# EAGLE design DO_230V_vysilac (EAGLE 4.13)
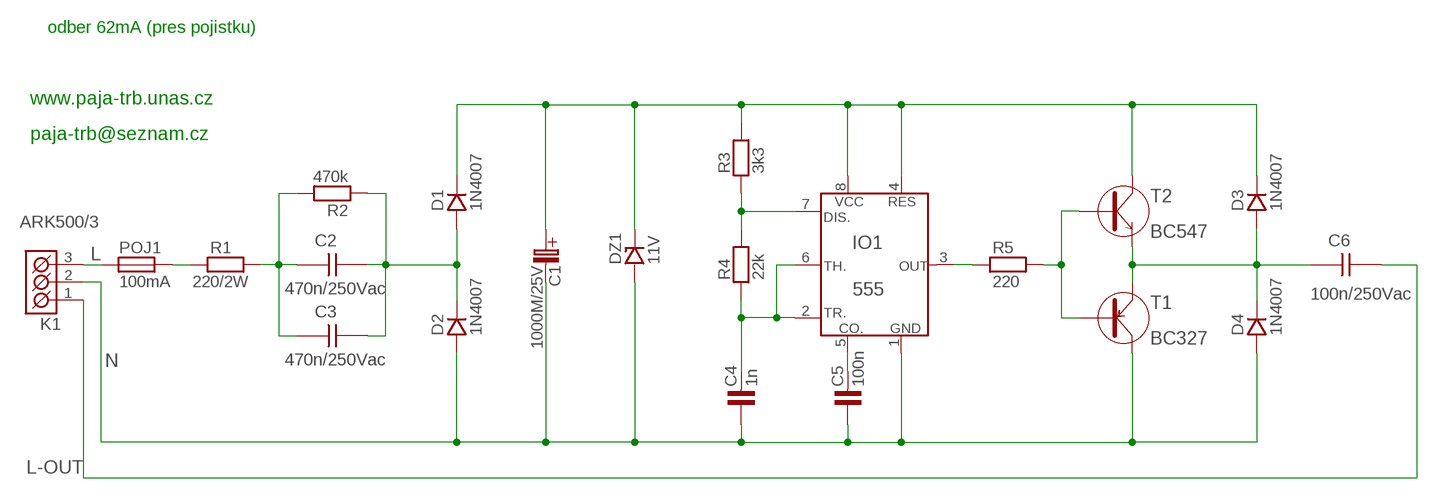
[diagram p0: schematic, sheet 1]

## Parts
C1  1000M/25V  [C_EL_5+]
C2  470n/250Vac  CFAC-15,0  [CFAC-15]
C3  470n/250Vac  CFAC-15,0  [CFAC-15]
C4  1n  C-KERAMIK_5  [C-5]
C5  100n  C-KERAMIK_5  [C-5]
C6  100n/250Vac  CFAC-15,0  [CFAC-15]
D1  1N4007  1N4007_10  [D-10]
D2  1N4007  1N4007_10  [D-10]
D3  1N4007  1N4007_10  [D-10]
D4  1N4007  1N4007_10  [D-10]
DZ1  11V  D-ZENEROVA_1,3W_BZX85V  [D-7,5]
IO1  555  [DIL8]
K1  ARK500/3  [ARK500/3]
POJ1  100mA  PO_SHH  [POJ_SHH]
R1  220/2W  R__2W  [R-_2W]
R2  470k  R_7,5  [R-7,5]
R3  3k3  R_7,5  [R-7,5]
R4  22k  R_7,5  [R-7,5]
R5  220  R_7,5  [R-7,5]
T1  BC327  [TO-92]
T2  BC547  BC546  [TO-92]

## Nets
A: C2.1 C3.1 R1.2 R2.2
L: K1.3(K3) POJ1.L1
L-IN: POJ1.P1 R1.1
L-OUT: C6.2 K1.1(K1)
N: C1.C-(C_EL-) C4.1 C5.1 D2.A D4.A DZ1.A IO1.1(GND) K1.2(K2) T1.1(C)
N$1: C4.2 IO1.2(TR.) IO1.6(TH.) R4.1
N$2: IO1.7(DIS.) R3.1 R4.2
N$4: IO1.3(OUT) R5.1
N$6: R5.2 T1.2(B) T2.2(B)
N$8: C6.1 D3.A D4.K T1.3(E) T2.3(E)
N$10: C5.2 IO1.5(CO.)
N$13: C1.C+(C_EL+) D1.K D3.K DZ1.K IO1.4(RES) IO1.8(VCC) R3.2 T2.1(C)
N$14: C2.2 C3.2 D1.A D2.K R2.1

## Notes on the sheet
- odber 62mA (pres pojistku)
- www.paja-trb.unas.cz
- paja-trb@seznam.cz

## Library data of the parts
C1 = #PaJa_C-el:1000M/25V
C2 C3 C6 = #_GM99:CFAC-15,0
C4 C5 = #PaJa_20:C-KERAMIK: Kondenzator - keramicky
D1-D4 = #PaJa_20:1N4007: Usmernovaci dioda - 1A, 1000V
DZ1 = #PaJa_20:D-ZENEROVA: Zenerova dioda
IO1 = #PaJa_20:555: IO - Casovac 555
K1 = #PaJa_20:ARK500/3: Svorkovnice - roztec 5mm - trojita
POJ1 = #PaJa_20:PO_SHH: Pojistkove pouzdro
R1-R5 = #PaJa_20:R: Rezistor
T1 = #PaJa_20:BC327: Tranzistor PNP - Univerzalni NF - Ic=0,5A
T2 = #PaJa_20:BC546: Tranzistor NPN - Univerzalni NF - Ic=0,1A

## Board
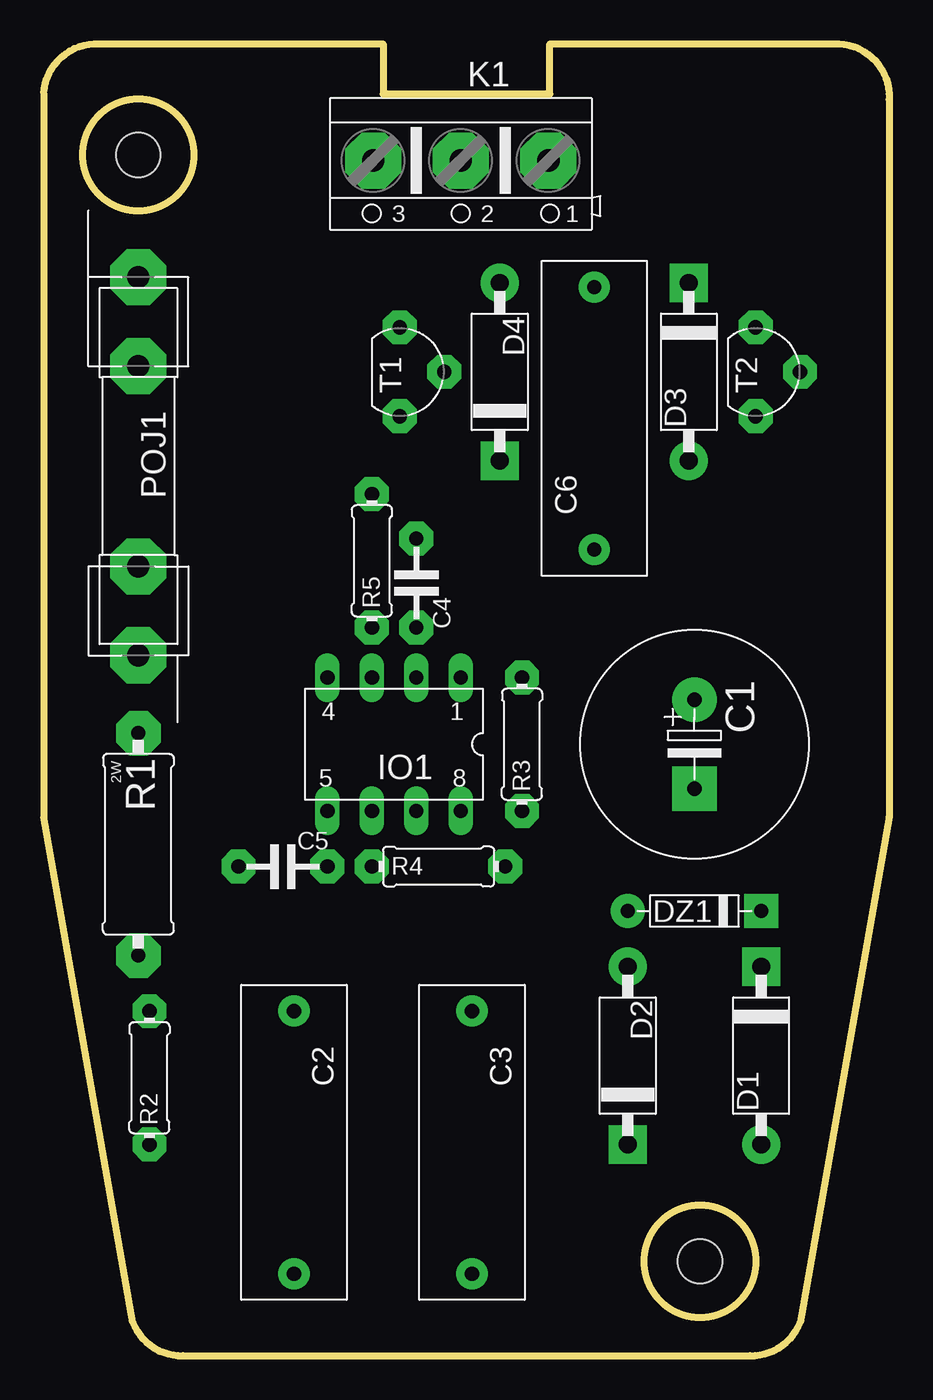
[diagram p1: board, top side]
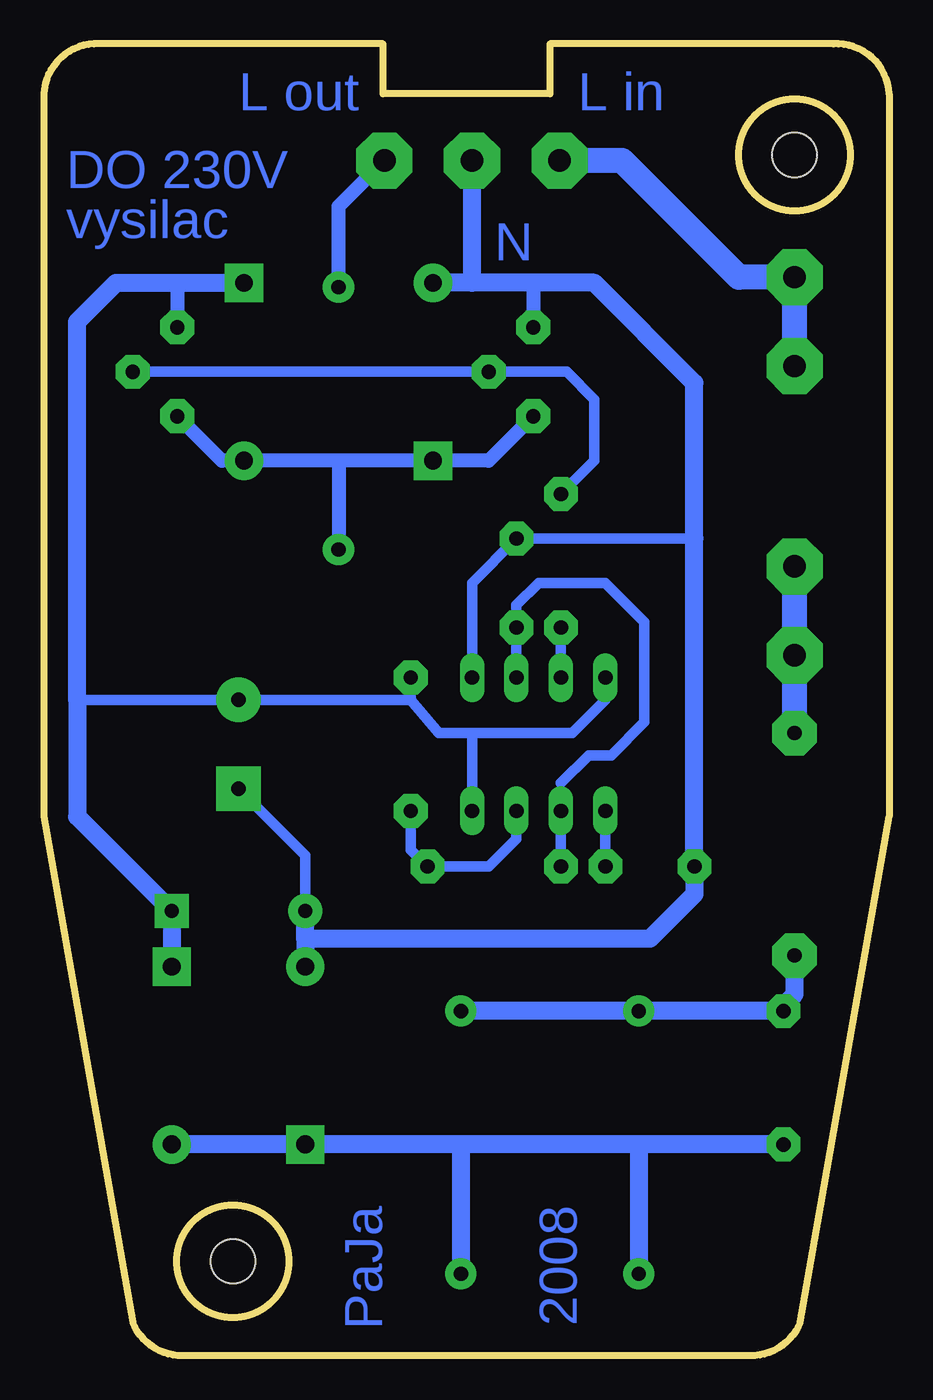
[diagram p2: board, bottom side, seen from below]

Size 48.26 x 74.93 mm. Coordinates in mm from the lower left corner, seen from the top.
Copper layers (1*16): Top 0.035mm / dielectric 1.5mm / Bottom 0.035mm
Design rules "default": minimum track width 10mil, minimum drill 24mil, track to track 8mil, track to pad 8mil, pad to pad 8mil, via to via 8mil, smd to smd 8mil, copper to edge 40mil, drill to drill 8mil, minimum pad ring 10mil, minimum via ring 8mil, stop-mask expansion 4mil, vias tented up to drill 0mil, thermal gap 10mil

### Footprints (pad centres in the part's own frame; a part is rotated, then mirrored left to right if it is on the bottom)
C_EL_5+ = drill 0.813 pad 2.54 round: C+ -2.54,0 | drill 0.813 pad 2.54 square: C- 2.54,0
CFAC-15 = drill 0.813 pad 1.778 round: 1 0,0; 2 15,0
C-5 = drill 0.813 pad 1.93 octagon: 1 -2.54,0; 2 2.54,0
D-10 = drill 1.016 pad 2.184 round: A -5.08,0 | drill 1.016 pad 2.184 square: K 5.08,0
D-7,5 = drill 0.813 pad 1.93 round: A -3.81,0 | drill 0.813 pad 1.93 square: K 3.81,0
DIL8 = drill 0.813 pad 1.4 long: 1 -3.81,-3.81; 2 -1.27,-3.81; 3 1.27,-3.81; 4 3.81,-3.81; 5 3.81,3.81; 6 1.27,3.81; 7 -1.27,3.81; 8 -3.81,3.81
ARK500/3 = drill 1.27 pad 3.2 octagon: 1 -5,0; 2 0,0; 3 5,0
POJ_SHH = drill 1.27 pad 3.2 octagon: L1 -10.795,0; L2 -5.715,0; P1 10.795,0; P2 5.715,0
R-_2W = drill 0.813 pad 2.54 octagon: 1 -6.35,0; 2 6.35,0
R-7,5 = drill 0.813 pad 1.93 octagon: 1 -3.81,0; 2 3.81,0
TO-92 = drill 0.813 pad 1.93 octagon: 1 0,2.54; 2 2.54,0; 3 0,-2.54
U-KPZ3 = hole 2.54: 13.335,-25.4; -18.733,37.782

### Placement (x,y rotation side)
C1  37.15,34.92 270 top
C2  14.29,19.68 270 top
C3  24.45,19.68 270 top
C4  21.27,44.13 270 top
C5  13.65,27.94 0 top
C6  31.43,46.04 90 top
D1  40.96,17.14 90 top
D2  33.34,17.14 270 top
D3  36.83,56.2 90 top
D4  26.03,56.2 270 top
DZ1  37.15,25.4 0 top
IO1  20,34.92 180 top
K1  23.81,68.26 180 top
POJ1  5.4,50.8 270 top
R1  5.4,29.21 270 top
R2  6.03,15.87 90 top
R3  27.3,34.92 90 top
R4  22.54,27.94 0 top
R5  18.73,45.4 90 top
T1  20.32,56.2 0 top
T2  40.64,56.2 0 top
U$1  [U-KPZ3]  24.13,30.8 0 top

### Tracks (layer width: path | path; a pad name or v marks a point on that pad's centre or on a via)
A
  Bottom 1.016: R1.2 5.4,20.64 6.35,19.68 R2.2 C2.1 C3.1
L
  Bottom 1.422: 5.4,56.51 POJ1.L1 8.57,61.6 15.24,68.26 K1.3
L-IN
  Bottom 1.422: R1.1 POJ1.P1 5.4,45.08
L-OUT
  Bottom 0.813: K1.1 31.43,65.64 C6.2
N
  Bottom 0.61: IO1.1 23.81,44.13 C4.1 11.11,46.67 | DZ1.A 33.34,28.57 C1.C-
  Bottom 0.813: 20.32,61.28 T1.1
  Bottom 1.016: 33.34,23.81 13.65,23.81 11.11,26.35 C5.1 11.11,46.67 11.11,55.56 16.83,61.28 20.32,61.28 23.81,61.28 | 33.34,23.81 DZ1.A | 33.34,23.81 D2.A | 23.81,61.28 K1.2 | 23.81,61.28 D4.A
N$1
  Bottom 0.406: IO1.6 18.73,32.7
  Bottom 0.61: R4.1 IO1.6 | IO1.2 C4.2 21.27,42.86 20,44.13 16.19,44.13 13.97,41.91 13.97,36.19 15.87,34.29 17.14,34.29 18.73,32.7
N$2
  Bottom 0.61: IO1.7 21.27,29.53 22.86,27.94 R4.2 27.3,28.89 R3.1
N$4
  Bottom 0.61: IO1.3 R5.1
N$6
  Bottom 0.61: T2.2 T1.2 18.41,56.2 16.83,54.61 16.83,51.12 R5.2
N$8
  Bottom 0.813: T1.3 22.86,51.12 D4.K 31.43,51.12 | T2.3 38.1,51.12 D3.A 31.43,51.12 | 31.43,51.12 C6.1
N$10
  Bottom 0.61: C5.2 IO1.5
N$13
  Bottom 0.61: 27.3,37.47 R3.2 | 27.3,37.47 25.72,35.56 23.81,35.56 | 23.81,35.56 18.1,35.56 16.19,37.47 IO1.4 | 23.81,35.56 IO1.8 | 27.3,37.47 C1.C+ 46.36,37.47
  Bottom 0.813: 40.64,61.28 T2.1
  Bottom 1.016: D1.K DZ1.K 46.36,30.8 46.36,37.47 46.36,59.06 44.13,61.28 40.64,61.28 D3.K
N$14
  Bottom 1.016: R2.1 14.29,12.06 | 14.29,12.06 24.45,12.06 | 24.45,12.06 D2.K D1.A | 24.45,12.06 C3.2 | 14.29,12.06 C2.2

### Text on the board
Bottom: L in | L out | DO 230V | vysilac | N | 2008 | PaJa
